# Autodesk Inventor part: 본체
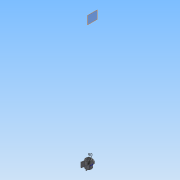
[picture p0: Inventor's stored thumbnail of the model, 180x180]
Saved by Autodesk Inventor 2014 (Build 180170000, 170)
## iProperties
Created: 2015-01
Part Number: 본체
Material: 일반
Document SubType Name: Modeling
Designer: net
Density: 1 g/cm^3
Appearance: 기본값
Author: net
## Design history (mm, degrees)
sketch "스케치1"
  geometry: C1 r 50 at (0, 0); 1 further point
  constraints: 1 centre point, 1 coincident
  dimensions: "d0" = 100 diameter of C1
extrude "돌출1" new body sketch "스케치1" distance "d1" = 112; taper "d2" = 0 deg
sketch "스케치2"
  geometry: C1 r 50 at (0, 0) reference; C2 r 38 at (0, 0)
  constraints: 1 centre point, 1 coincident
  dimensions: "d3" = 76 diameter of C2
extrude "돌출2" join sketch "스케치2" distance "d4" = 5; taper "d5" = 0 deg
node "작업 평면1"
sketch "스케치3"
  geometry: L1 (-50, 0)-(50, 0) reference; L2 (50, 0)-(50, 112) reference; C1 r 38 at (0, 56); 2 further points
  constraints: 1 centre point, 1 horizontal alignment, 1 midpoint, 1 vertical alignment
  dimensions: "d7" = 76 diameter of C1
extrude "돌출3" join sketch "스케치3" stored distance "d9" = 5; taper "d10" = 0 deg
sketch "스케치4"
  geometry: C1 r 50 at (0, 0) reference; C2 r 38 at (0, 0)
  constraints: 1 centre point, 1 coincident
  dimensions: "d11" = 76 diameter of C2
extrude "돌출4" join sketch "스케치4" distance "d12" = 5; taper "d13" = 0 deg
hole "구멍1" diameter "d16" = 54; stored, may be unused: countersink angle "d20" = 90 deg, drill point angle "d22" = 0 deg; dims "d14" = 10, "d15" = 10, "d17" = 6, "d18" = 4, "d19" = 2, "d21" = 12
node "작업 평면2"
sketch "스케치5"
  geometry: C1 r 45 at (0, 0); 1 further point
  constraints: 1 centre point, 1 coincident
  dimensions: "d23" = 90 diameter of C1
hole "구멍2" diameter "d28" = 54; stored, may be unused: countersink angle "d32" = 90 deg, drill point angle "d34" = 0 deg; dims "d26" = 10, "d27" = 10, "d29" = 6, "d30" = 4, "d31" = 2, "d33" = 13
sketch "스케치6" dims "d38" = 64
  geometry: C1 r 27 at (0, 0) reference; C2 r 38 at (0, 0) reference; 2 further points
  constraints: 2 vertical alignment, 1 coincident, 2 other
hole "구멍3" sketch "스케치6" at (0, 32) diameter "d39" = 3.459; stored, may be unused: countersink angle "d43" = 90 deg, drill point angle "d45" = 118 deg; dims "d40" = 8, "d41" = 4, "d42" = 2, "d44" = 10
sketch "스케치7" dims "d49" = 64
  geometry: C1 r 27 at (0, 0) reference; C2 r 38 at (0, 0) reference; 2 further points
  constraints: 2 vertical alignment, 1 coincident, 2 other
hole "구멍4" sketch "스케치7" at (0, 32) diameter "d50" = 3.459; stored, may be unused: countersink angle "d54" = 90 deg, drill point angle "d56" = 118 deg; dims "d51" = 8, "d52" = 4, "d53" = 2, "d55" = 10
sketch "스케치8" dims "d60" = 64
  geometry: C1 r 38 at (0, 0) reference; 3 further points
  constraints: 2 vertical alignment, 1 coincident, 2 other
hole "구멍5" sketch "스케치8" at (0, 32) diameter "d61" = 3.459; stored, may be unused: countersink angle "d65" = 90 deg, drill point angle "d67" = 118 deg; dims "d62" = 8, "d63" = 4, "d64" = 2, "d66" = 10
fillet "모깎기3" dims "d82" = 3
chamfer "모따기1" distance "d83" = 1; stored, may be unused: second distance "d84" = 2, angle "d85" = 45 deg
fillet "모깎기4" dims "d86" = 3
fillet "모깎기5" dims "d87" = 3
fillet "모깎기6" dims "d88" = 3
node "작업 평면5"
sketch "스케치10"
  geometry: L1 (-39.336, -30.865)-(-48, -80); L2 (-27.282, -41.901)-(-34, -80); L3 (-48, -80)-(-34, -80); C1 r 45 at (0, 0) reference; A1 r 50 centre (0, 0) between (-39.336, -30.865) and (-27.282, -41.901) reference; 1 further point
  constraints: 6 end point, 2 point on circle, 1 horizontal, 1 parallel
  dimensions: "d93" = 80 distance from line of point (0, 0) L3; "d94" = 100 deg angle of L3 L1; "d95" = 48 horizontal distance of point (0, 0) L1.end; "d128" = 14 distance of L2.end L1.end
extrude "돌출6" join sketch "스케치10" stored distance "d96" = 80; taper "d97" = 0 deg
fillet "모깎기7" dims "d98" = 3
fillet "모깎기8" dims "d99" = 3
node "작업 평면6"
node "작업 평면7"
sketch "스케치11"
  geometry: L1 (-6, 30)-(6, 30); L2 (6, 30)-(6, 84); L3 (6, 84)-(-6, 84); L4 (-6, 84)-(-6, 30); L5 (80, 19)-(80, 93) reference; L6 (50, 3)-(50, 109) reference; L7 (-6, 57)-(6, 57); L8 (-38, -5)-(38, -5) reference; 4 further points
  constraints: 10 end point, 5 midpoint, 3 horizontal, 2 vertical alignment, 1 coincident
  dimensions: "d101" = 54 distance of L3.end L1.start; "d102" = 12 distance between parallel lines of L2 L4; "d103" = 62 distance between parallel lines of L8 L7
extrude "돌출7" join sketch "스케치11" stored distance "d104" = 80; taper "d105" = 0 deg
sketch "스케치12"
  geometry: L1 (30, 6)-(30, -6) reference; L2 (-5, 38)-(-5, -38) reference; 3 further points
  constraints: 1 horizontal alignment, 1 midpoint, 1 other
  dimensions: "d106" = 62 distance from line of L2 point (57, 0)
feature "엠보싱1" sketch "스케치12" dims "d107" = 0.5, "d108" = 0
node "작업 평면9"
sketch "스케치14"
  geometry: C1 r 45 at (0, 0); 1 further point
  constraints: 1 centre point, 1 coincident
  dimensions: "d114" = 90 diameter of C1
extrude "돌출9" cut sketch "스케치14" distance "d115" = 97; taper "d116" = 0 deg
fillet "모깎기9" dims "d120" = 3
sketch "스케치17"
  geometry: C1 r 38 at (0, 0) reference; C2 r 27 at (0, 0); 1 further point
  constraints: 1 centre point, 1 coincident
  dimensions: "d121" = 54 diameter of C2
extrude "돌출11" cut sketch "스케치17" stored distance "d122" = 97; taper "d123" = 0 deg
fillet "모깎기10" dims "d124" = 3
chamfer "모따기2" distance "d125" = 1; stored, may be unused: second distance "d126" = 2, angle "d127" = 45 deg
sketch "스케치16"
  geometry: C1 r 45 at (0, 0); 1 further point
  constraints: 1 centre point, 1 coincident
  dimensions: "d117" = 90 diameter of C1
extrude "돌출10" join sketch "스케치16" distance "d118" = 97; taper "d119" = 0 deg
node "작업 평면8"
sketch "스케치13"
  geometry: C1 r 45 at (0, 0); 1 further point
  constraints: 1 centre point, 1 coincident
  dimensions: "d110" = 90 diameter of C1
extrude "돌출8" cut sketch "스케치13" distance "d111" = 97; taper "d112" = 0 deg
sketch "스케치9"
  geometry: L1 (32, 50.961)-(33.73, 52) reference; L2 (33.73, 52)-(33.73, 62) reference; L3 (33.73, 62)-(38, 62) reference; L4 (38, 62)-(38, 33.586) reference; L5 (-38, 33.586)-(-38, 62) reference; L6 (-38, 62)-(-33.73, 62) reference; L7 (-33.73, 62)-(-33.73, 52) reference; L8 (-33.73, 52)-(-32, 50.961) reference; L9 (-32, 50.961)-(-30.27, 52) reference; L10 (-30.27, 52)-(-30.27, 62) reference; L11 (-30.27, 62)-(-27, 62) reference; L12 (-27, 62)-(-27, 37.47) reference; L13 (27, 37.47)-(27, 62) reference; L14 (27, 62)-(30.27, 62) reference; L15 (30.27, 62)-(30.27, 52) reference; L16 (30.27, 52)-(32, 50.961) reference; L17 (-34.835, -28.487)-(-43.918, -80); L18 (-43.918, -80)-(-31.366, -80); L19 (-31.366, -80)-(-23.975, -38.082); A1 r 50 centre (0, 0) between (-38.679, 31.685) and (38.679, 31.685) reference; A2 r 45 centre (0, 0) between (-28.125, 35.128) and (28.125, 35.128) reference; 1 further point
  constraints: 6 end point, 2 point on circle, 1 horizontal, 4 other
  dimensions: "d89" = 100 deg angle of L18 L17; "d90" = 80 distance from line of point (0, 0) L18; "d91" = 80 deg angle of L19 L18
  node "절단 모서리 투영1"
node "작업 평면4"
  node "작업 평면3"
node "솔리드1"
pattern_circular "원형 패턴1" dims angle "d47" = 360 deg
pattern_circular "원형 패턴2" dims angle "d58" = 360 deg
pattern_circular "원형 패턴3" dims angle "d69" = 360 deg
mirror "대칭1"
other parameters: "d6" = 62, "d35" = 12, "d100" = 2, "d109" = -13, "d113" = -12
